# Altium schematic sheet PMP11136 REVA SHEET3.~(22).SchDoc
size 431 x 279 mm; Date: Not shown in title block; ApprovedBy: Not shown in title block; CheckedBy: Not shown in title block; Author: Not shown in title block; CompanyName: Not shown in title block; Engineer: Not shown in title block; Organization: Not shown in title block; Address1: Not shown in title block; Address2: Not shown in title block; Address3: Not shown in title block; Address4: Not shown in title block; DocumentNumber: 3; Revision: Use project parameter SCH_Rev; SheetNumber: 3; SheetTotal: 3; PageSetup: Record=PageOptions¦CenterHorizontal=True¦CenterVertical=True¦PrintScale=1.00¦XCorrection=1.00¦YCorrection=1.00¦PrintKind=0¦BorderSize=5000000¦LeftOffset=0¦BottomOffset=0¦Orientation=2¦PaperLength=1000¦PaperWidth=1000¦Scale=100¦PaperSource=15¦PrintQuality=600¦MediaType=1¦DitherType=10¦PaperKind=Letter¦PrintScaleMode=1
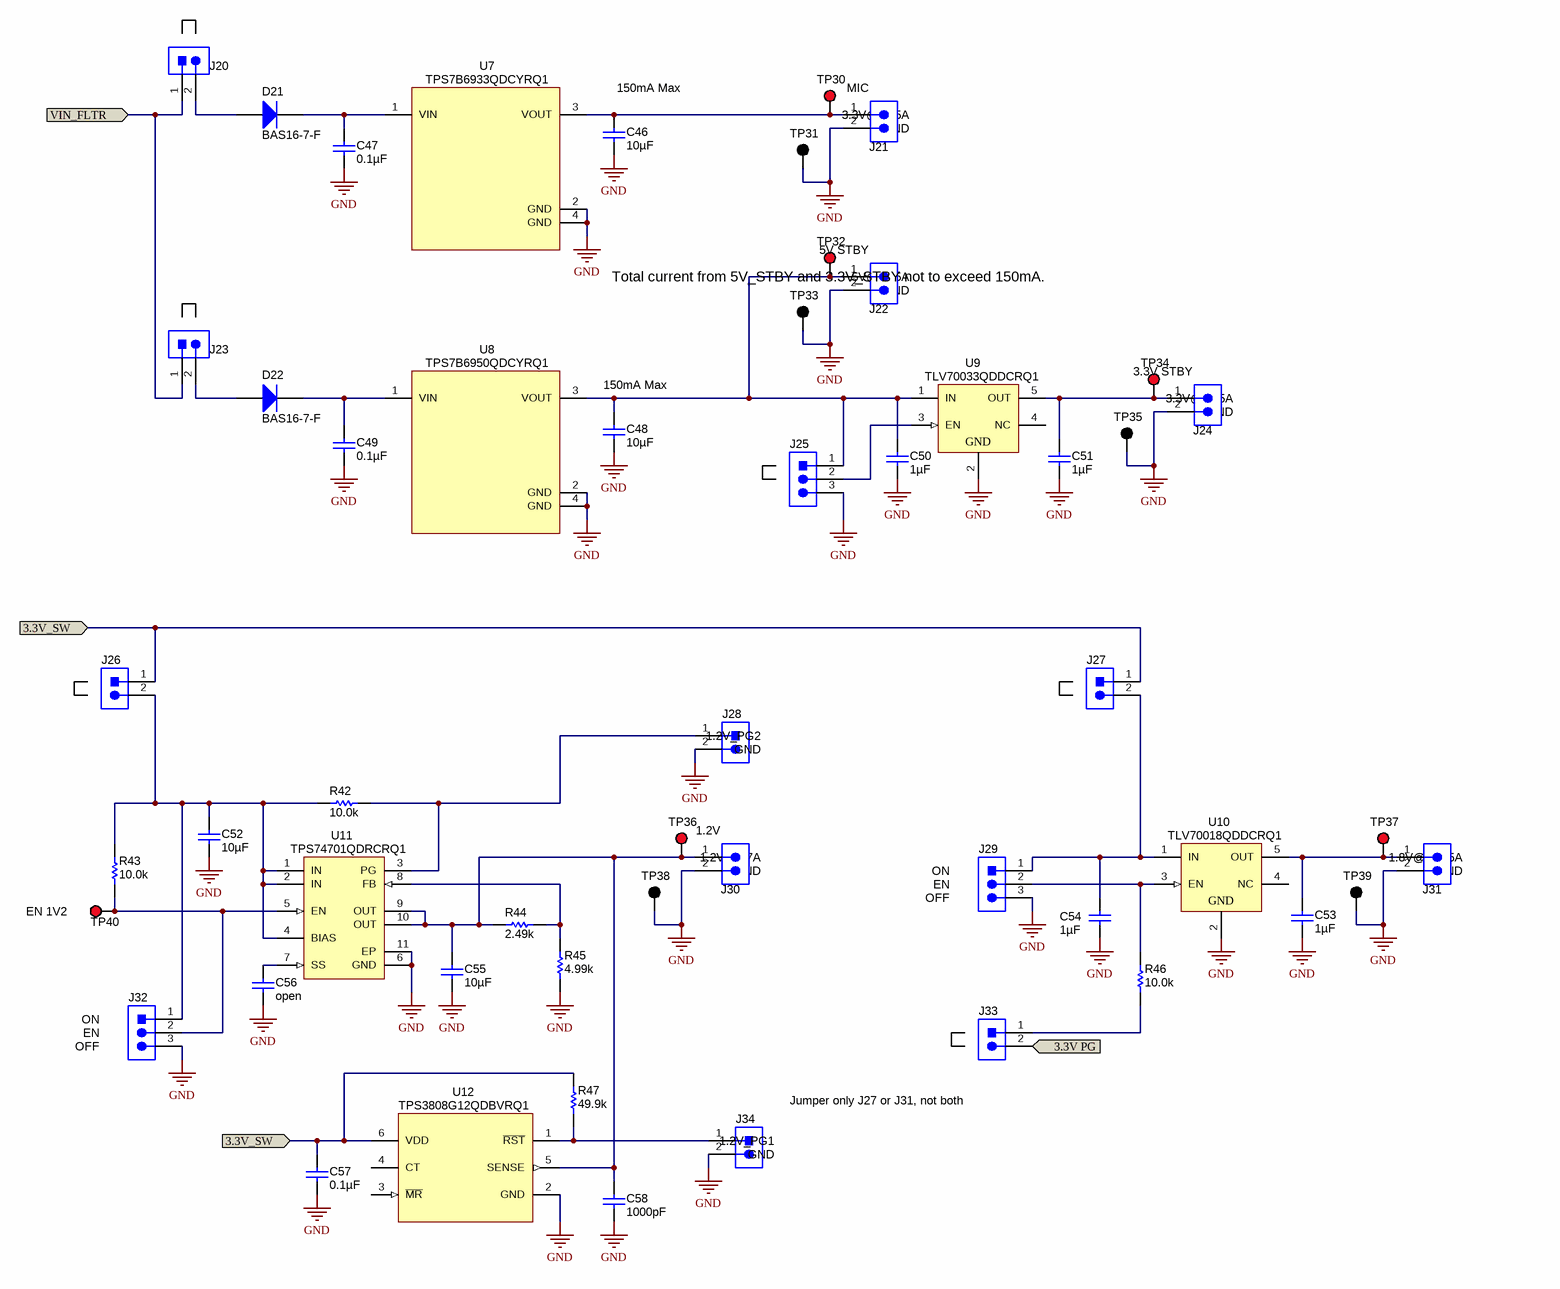
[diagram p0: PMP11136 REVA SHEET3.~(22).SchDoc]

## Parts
C46  ValueDisplayed: 10µF  [0805_HV]  (hidden comment: GRM21BR71A106KE51L)
C47  ValueDisplayed: 0.1µF  [0603]  (hidden comment: C1608X7R1H104K)
C48  ValueDisplayed: 10µF  [0805]  (hidden comment: GRM21BR71A106KE51L)
C49  ValueDisplayed: 0.1µF  [0603]  (hidden comment: C1608X7R1H104K)
C50  ValueDisplayed: 1µF  [0603]  (hidden comment: C1608X7R1E105K)
C51  ValueDisplayed: 1µF  [0603]  (hidden comment: C1608X7R1E105K)
C52  ValueDisplayed: 10µF  [0805_HV]  (hidden comment: GRM21BR71A106KE51L)
C53  ValueDisplayed: 1µF  [0603]  (hidden comment: C1608X7R1E105K)
C54  ValueDisplayed: 1µF  [0603]  (hidden comment: C1608X7R1E105K)
C55  ValueDisplayed: 10µF  [0805_HV]  (hidden comment: GRM21BR71A106KE51L)
C56  ValueDisplayed: open  [0603]
C57  ValueDisplayed: 0.1µF  [0603]  (hidden comment: C1608X7R1H104K)
C58  ValueDisplayed: 1000pF  [0603]  (hidden comment: C1608C0G2A102J)
D21  BAS16-7-F  [SOT-23]
D22  BAS16-7-F  [SOT-23]
J20  PEC02SAAN  [CONN_PEC02SAAN]  (value not drawn)
J21  ED555/2DS  [TERM_BLK_ED555-2DS]  (value not drawn)
J22  ED555/2DS  [TERM_BLK_ED555-2DS]  (value not drawn)
J23  PEC02SAAN  [CONN_PEC02SAAN]  (value not drawn)
J24  ED555/2DS  [TERM_BLK_ED555-2DS]  (value not drawn)
J25  PEC03SAAN  [CONN_PEC03SAAN]  (value not drawn)
J26  PEC02SAAN  [CONN_PEC02SAAN]  (value not drawn)
J27  PEC02SAAN  [CONN_PEC02SAAN]  (value not drawn)
J28  PEC02SAAN  [CONN_PEC02SAAN]  (value not drawn)
J29  PEC03SAAN  [CONN_PEC03SAAN]  (value not drawn)
J30  ED555/2DS  [TERM_BLK_ED555-2DS]  (value not drawn)
J31  ED555/2DS  [TERM_BLK_ED555-2DS]  (value not drawn)
J32  PEC03SAAN  [CONN_PEC03SAAN]  (value not drawn)
J33  PEC02SAAN  [CONN_PEC02SAAN]  (value not drawn)
J34  PEC02SAAN  [CONN_PEC02SAAN]  (value not drawn)
R42  ValueDisplayed: 10.0k  [0603]  (hidden comment: CRCW060310K0FKEA)
R43  ValueDisplayed: 10.0k  [0603]  (hidden comment: CRCW060310K0FKEA)
R44  ValueDisplayed: 2.49k  [0603]  (hidden comment: CRCW06032K49FKEA)
R45  ValueDisplayed: 4.99k  [0603]  (hidden comment: CRCW06034K99FKEA)
R46  ValueDisplayed: 10.0k  [0603]  (hidden comment: CRCW060310K0FKEA)
R47  ValueDisplayed: 49.9k  [0603]  (hidden comment: CRCW060349K9FKEA)
TP30  5000  [Keystone5000]  (value not drawn)
TP31  5001  [Keystone5001]  (value not drawn)
TP32  5000  [Keystone5000]  (value not drawn)
TP33  5001  [Keystone5001]  (value not drawn)
TP34  5000  [Keystone5000]  (value not drawn)
TP35  5001  [Keystone5001]  (value not drawn)
TP36  5000  [Keystone5000]  (value not drawn)
TP37  5000  [Keystone5000]  (value not drawn)
TP38  5001  [Keystone5001]  (value not drawn)
TP39  5001  [Keystone5001]  (value not drawn)
TP40  5000  [Keystone5000]  (value not drawn)
U7  TPS7B6933QDCYRQ1  [DCY0004A_N]
U8  TPS7B6950QDCYRQ1  [DCY0004A_N]
U9  TLV70033QDDCRQ1  [DDC0005A_N]
U10  TLV70018QDDCRQ1  [DDC0005A_N]
U11  TPS74701QDRCRQ1  [DRC0010A]
U12  TPS3808G12QDBVRQ1  [DBV0006A_N]

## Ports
3.3V PG, 3.3V_SW, VIN_FLTR

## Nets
GND: C46.2 C47.2 C48.2 C49.2 C50.2 C51.2 C52.2 C53.2 C54.2 C55.2 C56.2 C57.2 C58.2 J21.2 J22.2 J24.2 J25.3 J28.2 J29.3 J30.2 J31.2 J32.3 J34.2 R45.1 TP31.1 TP33.1 TP35.1 TP38.1 TP39.1 U7.2(GND) U7.4(GND) U8.2(GND) U8.4(GND) U9.2(GND) U10.2(GND) U11.6(GND) U11.11(EP) U12.2(GND)
3.3V PG: J33.2 ; port 3.3V PG
3.3V_SW: C57.1 J26.1 J27.1 R47.2 U12.6(VDD) ; port 3.3V_SW
VIN_FLTR: J20.1 J23.1 ; port VIN_FLTR
NetC46_1: C46.1 J21.1 TP30.1 U7.3(VOUT)
NetC47_1: C47.1 D21.3(K) U7.1(VIN)
NetC48_1: C48.1 C50.1 J22.1 J25.1 TP32.1 U8.3(VOUT) U9.1(IN)
NetC49_1: C49.1 D22.3(K) U8.1(VIN)
NetC51_1: C51.1 J24.1 TP34.1 U9.5(OUT)
NetC52_1: C52.1 J26.2 J32.1 R42.2 R43.2 U11.1(IN) U11.2(IN) U11.4(BIAS)
NetC53_1: C53.1 J31.1 TP37.1 U10.5(OUT)
NetC54_1: C54.1 J27.2 J29.1 U10.1(IN)
NetC55_1: C55.1 C58.1 J30.1 R44.2 TP36.1 U11.9(OUT) U11.10(OUT) U12.5(SENSE)
NetC56_1: C56.1 U11.7(SS)
NetD21_1: D21.1(A) J20.2
NetD22_1: D22.1(A) J23.2
NetJ25_2: J25.2 U9.3(EN)
NetJ28_1: J28.1 R42.1 U11.3(PG)
NetJ29_2: J29.2 R46.2 U10.3(EN)
NetJ32_2: J32.2 R43.1 TP40.1 U11.5(EN)
NetJ33_1: J33.1 R46.1
NetJ34_1: J34.1 R47.1 U12.1(~{RST})
NetR44_1: R44.1 R45.2 U11.8(FB)

Not connected (* = marked no-connect by the designer): U9 4(NC); U10 4(NC); U12 3(~{MR}) 4(CT)

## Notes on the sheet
- 150mA Max
- (near J21) MIC
- (near J21) 3.3V@0.05A
- (near J21) GND
- (near J22) 5V STBY
- (near J22) 5V@0.15A
- (near J22) GND
- Total current from 5V_STBY and 3.3V_STBY not to exceed 150mA.
- (near J24) 3.3V STBY
- (near J24) 3.3V@0.05A
- (near J24) GND
- (near J28) 1.2V_PG2
- (near J28) GND
- (near J30) 1.2V
- (near J30) 1.2V@0.7A
- (near J31) 1.8V@0.155A
- EN 1V2
- (near J30) GND
- (near J29) EN
- (near J29) ON
- (near J29) OFF
- (near J31) GND
- (near J32) EN
- (near J32) ON
- (near J32) OFF
- (near J33) Jumper only J27 or J31, not both
- (near J34) 1.2V_PG1
- (near J34) GND

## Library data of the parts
C46 C52 C55 = GRM21BR71A106KE51L: CAP, CERM, 10 µF, 10 V, +/- 10%, X7R, 0805; Manufacturer: MuRata; Polarized: N; CompType: Capacitor; Value: 10uF; U/M: EA; Cap_F: 0.00001; Tolerance_%: 10; ESR_ohm: 0.003; Value1: 0.003 ohm; Value2: 10V; TaMin_C: -55; TaMax_C: 125; Cap_Case: 0805
C47 C49 C57 = C1608X7R1H104K: CAP, CERM, 0.1uF, 50V, +/-10%, X7R, 0603; Manufacturer: TDK; Polarized: N; CompType: Capacitor; U/M: EA; Cap_F: 0.0000001; Tolerance_%: 10; ESR_Ohm: 0.017; Value1: 0.017 ohm; VDC_V: 50; TaMin_C: -55; TaMax_C: 125
C48 = GRM21BR71A106KE51L: CAP, CERM, 10uF, 10V, +/-10%, X7R, 0805; Manufacturer: MuRata; Polarized: N; CompType: Capacitor; U/M: EA; Cap_F: 0.00001; Tolerance_%: 10; ESR_Ohm: 0.003; Value1: 0.003 ohm; TaMin_C: -55; TaMax_C: 125
C50 C51 C53 C54 = C1608X7R1C105K: CAP, CERM, 1uF, 25V, +/-10%, X7R, 0603; Manufacturer: TDK; Polarized: N; CompType: Capacitor; U/M: EA; Cap_F: 0.000001; Tolerance_%: 10; ESR_Ohm: 0.0057; Value1: 0.0057 ohm; VDC_V: 25; TaMin_C: -55; TaMax_C: 125
C56 = C1608C0G1H102J: CAP, CERM, open, 0603; Polarized: N; CompType: Capacitor; U/M: EA; Cap_F: 0.000000001; Tolerance_%: 5; ESR_ohm: 0.0563; TempCo: C0G/NP0; TaMin_C: -55; TaMax_C: 125
C58 = C1608C0G2A102J: CAP, CERM, 1000 pF, 100 V, +/- 5%, C0G/NP0, 0603; Manufacturer: TDK; Polarized: N; CompType: Capacitor; Value: 1000pF; U/M: EA; Cap_F: 0.000000001; Tolerance_%: 5; ESR_ohm: 0.0589; Value1: 0.0589 ohm; VDC_V: 100; Value2: 100V; TaMin_C: -55; TaMax_C: 125
D21 D22 = BAS16-7-F: Diode, Ultrafast, 75V, 0.3A, SOT-23; Manufacturer: Diodes Inc.; U/M: EA; Vf_V: 1.125; Value2: 1.125V; Io_A: 0.3; Vr_V: 75
J20 J23 J26-J28 J33 J34 = PEC02SAAN: Header, 100mil, 2x1, Tin, TH; Manufacturer: Sullins Connector Solutions; SymbolCreator: a0412235; U/M: EA
J21 J22 J24 J30 J31 = ED555/2DS: Terminal Block, 6A, 3.5mm Pitch, 2-Pos, TH; Manufacturer: On-Shore Technology, Inc.; SymbolCreator: a0412235; CompType: Connector; U/M: EA
J25 J29 J32 = PEC03SAAN: Header, 100mil, 3x1, Tin, TH; Manufacturer: Sullins Connector Solutions; SymbolCreator: a0799628; U/M: EA
R42 R43 R46 = CRCW060310K0FKEA: RES, 10.0 k, 1%, 0.1 W, 0603; Manufacturer: Vishay-Dale; CompType: Resistor; Value: 10.0k; Res_ohm: 10000; Value_Code: 10k0; Tolerance_%: 1; Power_W: 0.1; Value2: 0.1W; VDC_V: 75; TempCo: 100 ppm/C; EIA_Code: E96; U/M: EA
R44 = CRCW06032K49FKEA: RES, 2.49 k, 1%, 0.1 W, 0603; Manufacturer: Vishay-Dale; CompType: Resistor; Value: 2.49k; Res_ohm: 2490; Value_Code: 2k49; Tolerance_%: 1; Power_W: 0.1; Value2: 0.1W; VDC_V: 75; TempCo: 100 ppm/C; EIA_Code: E96; U/M: EA
R45 = CRCW06034K99FKEA: RES, 4.99 k, 1%, 0.1 W, 0603; Manufacturer: Vishay-Dale; CompType: Resistor; Value: 4.99k; Res_ohm: 4990; Value_Code: 4k99; Tolerance_%: 1; Power_W: 0.1; Value2: 0.1W; VDC_V: 75; TempCo: 100 ppm/C; EIA_Code: E96; U/M: EA
R47 = CRCW060349K9FKEA: RES, 49.9 k, 1%, 0.1 W, 0603; Manufacturer: Vishay-Dale; CompType: Resistor; Value: 49.9k; Res_ohm: 49900; Value_Code: 49k9; Tolerance_%: 1; Power_W: 0.1; Value2: 0.1W; VDC_V: 75; TempCo: 100 ppm/C; EIA_Code: E96; U/M: EA
TP30 TP32 TP34 TP36 TP37 TP40 = 5000: Test Point, TH, Miniature, Red; Manufacturer: Keystone; CompType: Test Point Loop; U/M: EA
TP31 TP33 TP35 TP38 TP39 = 5001: Test Point, TH, Miniature, Black; Manufacturer: Keystone; CompType: Test Point Loop; U/M: EA
U7 = TPS7B6933QDCYRQ1: High Voltage Ultra Low Iq - Low Drop Out Regulator, DCY0004A; Manufacturer: Texas Instruments; SymbolCreator: Altium; CompType: IC; U/M: EA
U8 = TPS7B6950QDCYRQ1: High Voltage Ultra Low Iq - Low Drop Out Regulator, DCY0004A; Manufacturer: Texas Instruments; SymbolCreator: Altium; CompType: IC; U/M: EA
U9 = TLV70033QDDCRQ1: Single Output Automotive LDO, 200 mA, Fixed 3.3 V Output, 2 to 5.5 V Input, with Low IQ, 5-pin SOT (DDC), -40 to 125 degC, Green (RoHS & no Sb/Br); Manufacturer: Texas Instruments; Alternate Manufacturer: None; Alternate PartNumber: Equivalent; Accuracy(%): 2; Fixed Output Options(V): 3.3; Iout(Max)(A): 0.2; Iq(Typ)(mA): 0.03; SubFamily: Single Channel LDO; Vdo(Typ)(mV): 175; Vin(Max)(V): 5.5
U10 = TLV70018QDDCRQ1: Single Output Automotive LDO, 300 mA, Fixed 1.8 V Output, 2 to 5.5 V Input, with Low IQ, 5-pin SOT (DDC), -40 to 125 degC, Green (RoHS & no Sb/Br); Manufacturer: Texas Instruments; Alternate Manufacturer: None; Alternate PartNumber: Equivalent; Accuracy(%): 2; Fixed Output Options(V): 1.8; Iout(Max)(A): 0.2; Iq(Typ)(mA): 0.03; SubFamily: Single Channel LDO; Vdo(Typ)(mV): 175; Vin(Max)(V): 5.5
U11 = TPS74701QDRCRQ1: Single Output Automotive LDO, 500 mA, Adjustable 0.8 to 3.6 V Output, 0.8 to 5.5 V Input, with Programmable Soft Start, 10-pin SON (DRC), -40 to 125 degC, Green (RoHS & no Sb/Br); Manufacturer: Texas Instruments; Alternate Manufacturer: None; Alternate PartNumber: Equivalent; Accuracy(%): 2; Iout(Max)(A): 0.5; Iq(Typ)(mA): 1; SubFamily: Single Channel LDO; Vdo(Typ)(mV): 50; Vin(Max)(V): 5.5; Vin(Min)(V): 0.8; Vout Adj(Max)(V): 3.6
U12 = TPS3808G18QDBVRQ1: LOW-QUIESCENT-CURRENT PROGRAMMABLE-DELAY SUPERVISORY CIRCUIT, DBV0006A; Manufacturer: Texas Instruments; SymbolCreator: Altium; CompType: IC; U/M: EA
